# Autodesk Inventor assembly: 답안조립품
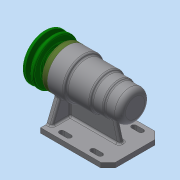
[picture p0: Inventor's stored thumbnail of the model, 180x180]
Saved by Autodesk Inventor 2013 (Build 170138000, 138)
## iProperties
Created: 2017-09
Part Number: 답안조립품
Document SubType Name: Assembly
Designer: Administrator
Author: Administrator
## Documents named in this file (12)
- C:\Users\Administrator\Desktop\470907V1011\답안조립품.iam
- C:\Users\Administrator\Desktop\470907V1011\본체.ipt
- C:\Users\Administrator\Desktop\470907V1011\470907V1011 (2)\V벨트풀리.ipt
- C:\Users\Administrator\Desktop\470907V1011\470907V1011 (2)\멈춤나사 M3x8.ipt
- C:\Users\Administrator\Desktop\470907V1011\470907V1011 (2)\베어링 6004.ipt
- C:\Users\Administrator\Desktop\470907V1011\470907V1011 (2)\베어링 51202.ipt
- C:\Users\Administrator\Desktop\470907V1011\470907V1011 (2)\볼트 M4 x 12.ipt
- C:\Users\Administrator\Desktop\470907V1011\470907V1011 (2)\어댑터슬리브.ipt
- C:\Users\Administrator\Desktop\470907V1011\470907V1011 (2)\오일 실 20x35x7.ipt
- C:\Users\Administrator\Desktop\470907V1011\470907V1011 (2)\축.ipt
- C:\Users\Administrator\Desktop\470907V1011\470907V1011 (2)\커버.ipt
- C:\Users\Administrator\Desktop\470907V1011\470907V1011 (2)\키 5 x 5 x 16.ipt
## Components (1 placed, 1 different names)
1. V벨트풀리:1
